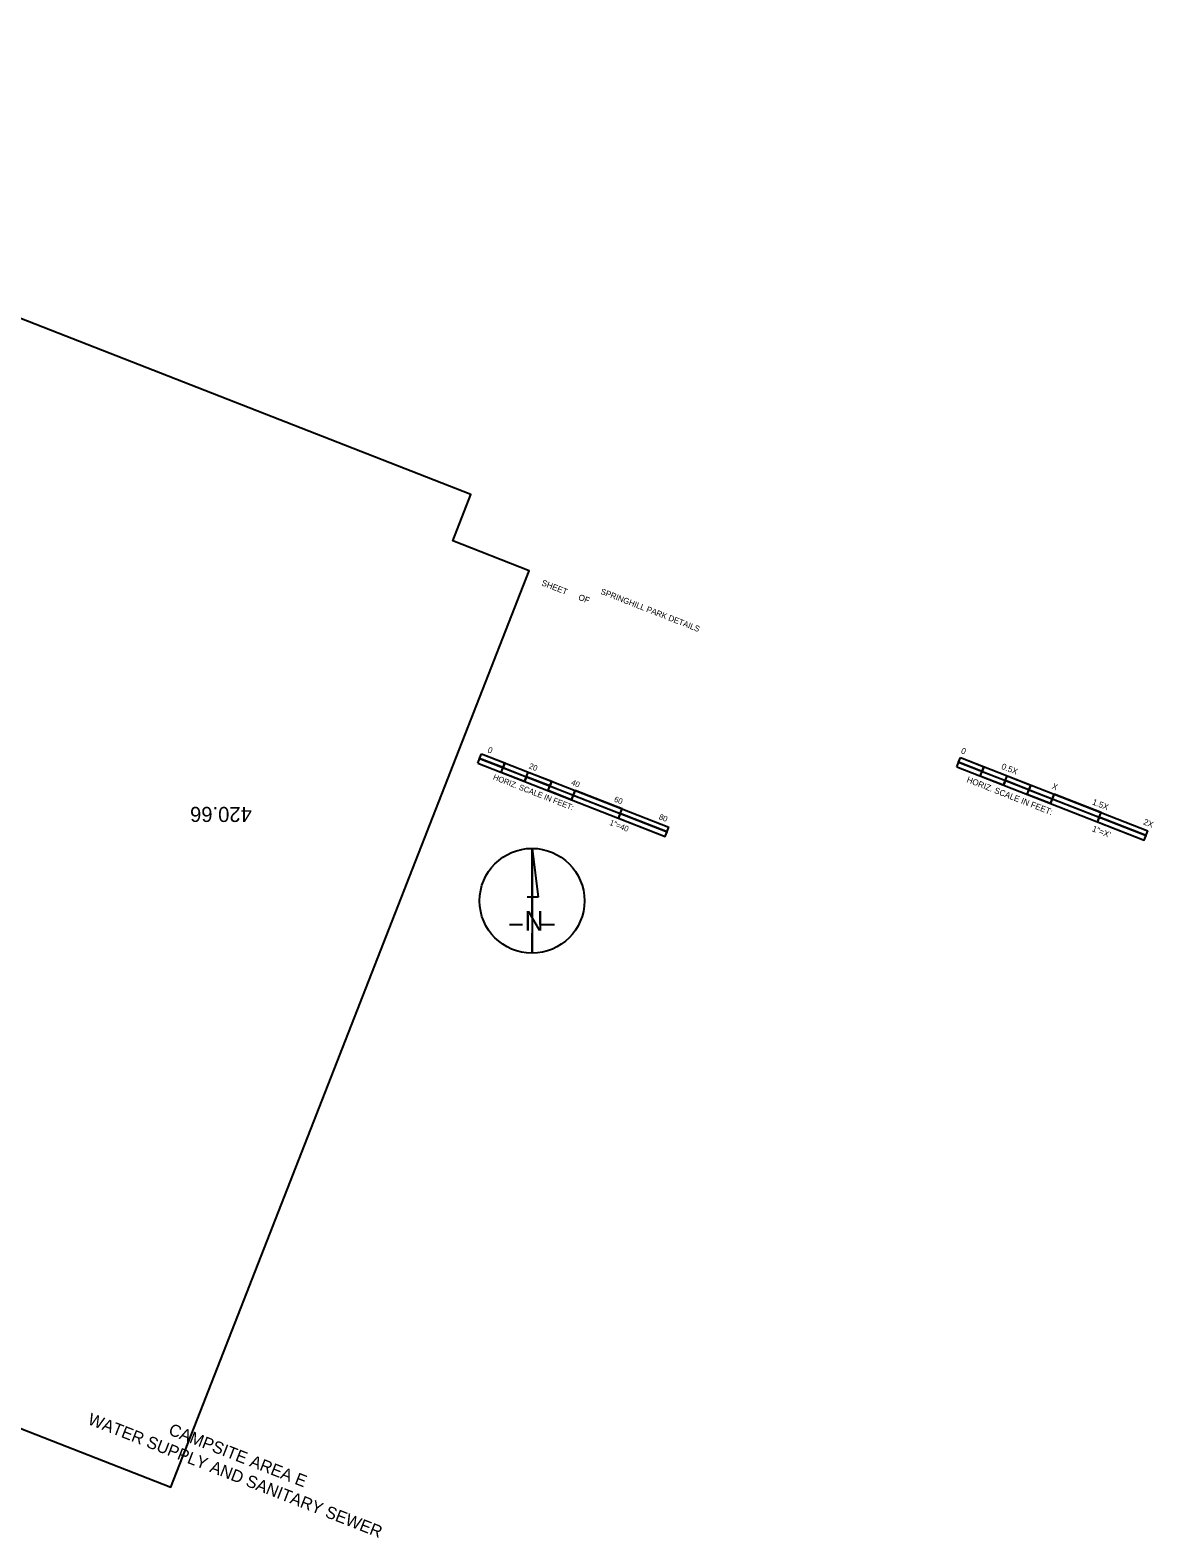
# Model space of a CAD drawing. Extents: x 626524 to 627418, y 376466 to 377065.
import ezdxf

# ---------------------------------------------------------------- set-up
doc = ezdxf.new("R2010")
doc.units = 0
for name, color, linetype in [('B_Bearing', 7, 'Continuous'), ('H_Horz Alg Drainage Control', 7, 'Continuous'), ('R_Horz Alg Driveway Control', 7, 'Continuous'), ('R_Temp Easement', 7, 'Continuous'), ('S_EXIST_ROW', 7, 'Continuous')]:
    doc.layers.add(name, color=color, linetype=linetype)

# ---------------------------------------------------------------- blocks, each defined once
blk = doc.blocks.new('SHT-INFO-CELL')
at = {"layer": 'H_Horz Alg Drainage Control'}
for s, p in [('SHEET', (14.441, 10.054)), ('OF', (14.833, 10.054))]:
    blk.add_text(s, height=0.06, dxfattribs=at).set_placement(p)

msp = doc.modelspace()

# ---------------------------------------------------------------- linework, layer by layer
at = {"layer": 'H_Horz Alg Drainage Control'}
for p, q in [((627339.24, 376771.98), (627340.7, 376775.7)), ((627339.24, 376771.98), (627413.75, 376742.84)), ((627339.97, 376773.84), (627414.48, 376744.71)), ((627340.7, 376775.7), (627415.21, 376746.57)), ((627340.7, 376775.7), (627377.95, 376761.14)), ((627348.55, 376768.33), (627350.01, 376772.06)), ((627357.87, 376764.69), (627359.32, 376768.42)), ((627367.18, 376761.05), (627368.64, 376764.78)), ((627376.5, 376757.41), (627377.95, 376761.14)), ((627395.12, 376750.13), (627396.58, 376753.85)), ((627413.75, 376742.84), (627415.21, 376746.57)), ((627170.39, 376739.62), (627170.39, 376697.96))]:
    msp.add_line(p, q, dxfattribs=at)
for points in [[(626673.79, 377064.86), (626524.18, 376682.16), (627026.79, 376485.68), (627169.21, 376849.96), (627138.89, 376861.88), (627146.09, 376880.3)], [(627340.7, 376775.7), (627350.01, 376772.06), (627349.28, 376770.2), (627339.97, 376773.84)], [(627349.28, 376770.2), (627358.6, 376766.56), (627357.87, 376764.69), (627348.55, 376768.33)], [(627359.32, 376768.42), (627368.64, 376764.78), (627367.91, 376762.91), (627358.6, 376766.56)], [(627367.91, 376762.91), (627377.22, 376759.27), (627376.5, 376757.41), (627367.18, 376761.05)], [(627377.22, 376759.27), (627395.85, 376751.99), (627396.58, 376753.85), (627377.95, 376761.14)], [(627395.12, 376750.13), (627413.75, 376742.84), (627414.48, 376744.71), (627395.85, 376751.99)]]:
    msp.add_lwpolyline(points, close=True, dxfattribs=at)
msp.add_circle((627170.39, 376718.79), 20.83, dxfattribs=at)
at = {"layer": 'R_Horz Alg Driveway Control'}
for p, q in [((627148.83, 376773.48), (627150.29, 376777.21)), ((627150.29, 376777.21), (627224.79, 376748.08)), ((627150.29, 376777.21), (627187.54, 376762.64)), ((627148.83, 376773.48), (627223.34, 376744.35)), ((627149.56, 376775.35), (627224.06, 376746.22)), ((627158.14, 376769.84), (627159.6, 376773.57)), ((627167.46, 376766.2), (627168.91, 376769.93)), ((627176.77, 376762.56), (627178.23, 376766.29)), ((627186.08, 376758.92), (627187.54, 376762.64)), ((627204.71, 376751.64), (627206.17, 376755.36)), ((627223.34, 376744.35), (627224.79, 376748.08))]:
    msp.add_line(p, q, dxfattribs=at)
for points in [[(627150.29, 376777.21), (627159.6, 376773.57), (627158.87, 376771.71), (627149.56, 376775.35)], [(627158.87, 376771.71), (627168.18, 376768.06), (627167.46, 376766.2), (627158.14, 376769.84)], [(627168.91, 376769.93), (627178.23, 376766.29), (627177.5, 376764.42), (627168.18, 376768.06)], [(627177.5, 376764.42), (627186.81, 376760.78), (627186.08, 376758.92), (627176.77, 376762.56)], [(627186.81, 376760.78), (627205.44, 376753.5), (627206.17, 376755.36), (627187.54, 376762.64)], [(627204.71, 376751.64), (627223.34, 376744.35), (627224.06, 376746.22), (627205.44, 376753.5)]]:
    msp.add_lwpolyline(points, close=True, dxfattribs=at)
at = {"layer": 'S_EXIST_ROW'}
for p, q in [((627170.39, 376739.62), (627172.82, 376720.23)), ((627170.39, 376712.51), (627170.39, 376739.62)), ((627168.51, 376720.37), (627172.82, 376720.37)), ((627161.48, 376709.31), (627166.62, 376709.31)), ((627170.39, 376697.96), (627170.39, 376705.93)), ((627173.82, 376709.31), (627179.31, 376709.31))]:
    msp.add_line(p, q, dxfattribs=at)

# ---------------------------------------------------------------- block references
at = {"layer": 'R_Temp Easement', "xscale": 39.99999999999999, "yscale": 39.99999999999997, "rotation": -21.35544218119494}
msp.add_blockref('SHT-INFO-CELL', (626489.54, 376680.04), dxfattribs=at)

# ---------------------------------------------------------------- texts
at = {"layer": 'B_Bearing'}
for s, height, p in [('SPRINGHILL PARK DETAILS', 2.3446, (627197.41, 376840.86)), ('WATER SUPPLY AND SANITARY SEWER', 4.8, (626993.44, 376510.9)), ('CAMPSITE AREA E', 4.8, (627025.53, 376506.74))]:
    msp.add_text(s, height=height, rotation=338.64456, dxfattribs=at).set_placement(p)
at = {"layer": 'H_Horz Alg Drainage Control'}
for s, height, rotation, p in [('OF', 2.4, 338.64456, (627188.59, 376838.55)), ('0', 2.4, 338.64451, (627340.69, 376777.55)), ('0.5X', 2.4, 338.64451, (627356.75, 376771.27)), ('HORIZ. SCALE IN FEET:', 2.4, 338.64451, (627342.95, 376766.02)), ('X', 2.4, 338.64451, (627376.81, 376763.43)), ('1.5X', 2.4, 338.64451, (627392.86, 376757.15)), ('420.66 ', 6, 180, (627059.01, 376756.12)), ('1"=X\'', 2.4, 338.64451, (627392.82, 376746.52)), ('2X', 2.4, 338.64451, (627413.18, 376749.21))]:
    msp.add_text(s, height=height, rotation=rotation, dxfattribs=at).set_placement(p)
at = {"layer": 'R_Horz Alg Driveway Control'}
for s, height, p in [('0', 2.4, (627152.49, 376777.87)), ('20', 2.25, (627168.94, 376771.51)), ('HORIZ. SCALE IN FEET:', 2.25, (627154.68, 376767.1)), ('40', 2.25, (627185.74, 376764.94)), ('40', 2.25, (627185.74, 376764.94)), ('60', 2.25, (627202.79, 376758.28)), ('80', 2.25, (627220.62, 376751.31)), ('1"=40', 2.25, (627200.98, 376749))]:
    msp.add_text(s, height=height, rotation=338.64451, dxfattribs=at).set_placement(p)
at = {"layer": 'S_EXIST_ROW'}
msp.add_text('N', height=7.76, rotation=360, dxfattribs=at).set_placement((627167.45, 376706.92))

doc.saveas('drawing.dxf')
